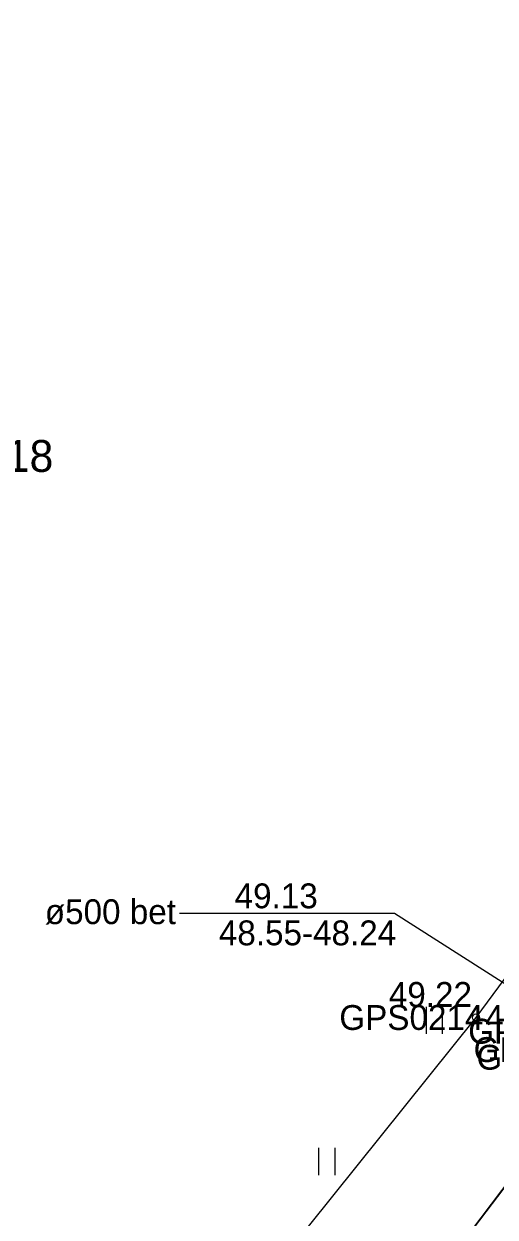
# Model space of a CAD drawing. Extents: x 563121 to 567545, y 6570841 to 6581299.
# Drawn here: x 565782.93 to 565796.21, y 6571844.15 to 6571877.77 of the extents above; entities that cross this region are included whole.
import ezdxf

# ---------------------------------------------------------------- set-up
doc = ezdxf.new("R2010")
doc.units = 0
for name, color, linetype in [('HALJASTUS', 7, 'Continuous'), ('KORGUS-EH2000', 7, 'Continuous'), ('MOOTKORG-EH2000', 7, 'Continuous'), ('MOOTMPUNKT', 7, 'Continuous'), ('MOOTNR', 7, 'Continuous'), ('MOOTPIIR', 7, 'Continuous'), ('PIIR', 7, 'Continuous'), ('TRUUP', 7, 'Continuous')]:
    doc.layers.add(name, color=color, linetype=linetype)

msp = doc.modelspace()

# ---------------------------------------------------------------- linework, layer by layer
at = {"layer": 'HALJASTUS'}
for p, q in [((565794.266, 6571850.073), (565794.266, 6571849.312)), ((565794.721, 6571850.073), (565794.721, 6571849.312)), ((565791.235, 6571846.096), (565791.235, 6571845.335)), ((565791.69, 6571846.096), (565791.69, 6571845.335))]:
    msp.add_line(p, q, dxfattribs=at)
at = {"layer": 'KORGUS-EH2000'}
msp.add_circle((565795.67, 6571849.773), 0.1, dxfattribs=at)
at = {"layer": 'MOOTMPUNKT'}
msp.add_circle((565795.67, 6571849.773), 0.1, dxfattribs=at)
at = {"layer": 'MOOTPIIR'}
msp.add_lwpolyline([(565823.283, 6571871.288), (565820.939, 6571873.864), (565815.364, 6571875.639), (565813.463, 6571874.16), (565808.89, 6571868.083), (565802.021, 6571858.377), (565795.67, 6571849.773), (565782.207, 6571833.008), (565776.308, 6571825.832), (565781.278, 6571820.922), (565782.262, 6571820.691), (565783.542, 6571819.443), (565784.347, 6571818.115), (565785.017, 6571817.401), (565789.374, 6571812.429), (565790.175, 6571811.534), (565801.221, 6571799.668)], dxfattribs=at)
at = {"layer": 'PIIR'}
msp.add_lwpolyline([(564959.63, 6571567.88), (565247.22, 6571575.87), (565310, 6571592), (565385.09, 6571617.94), (565603.34, 6571696.36), (565663.71, 6571724.88), (565720.01, 6571762.52), (565767.05, 6571806.3), (565831.51, 6571891.07), (565894.85, 6571978.6), (565929.68, 6572026.82), (566028.25, 6572163.26), (566043.71, 6572184.75), (566068.58, 6572219.3), (566114.67, 6572283.35)], dxfattribs=at)
msp.add_lwpolyline([(565385.09, 6571617.94), (565348.3, 6571706.93), (565808.88, 6572174.3), (565817.95, 6572187.54), (565914.67, 6572223.63), (565927.34, 6572201.79), (566013.66, 6572213.36), (566028.25, 6572163.26), (565929.68, 6572026.82), (565869.35, 6572071.5), (565833.75, 6572019.48), (565773.79, 6571931.89), (565831.51, 6571891.07), (565767.05, 6571806.3), (565720.01, 6571762.52), (565663.71, 6571724.88), (565603.34, 6571696.36)], close=True, dxfattribs=at)
at = {"layer": 'TRUUP'}
msp.add_lwpolyline([(565800.195, 6571848.355), (565793.374, 6571852.7), (565787.316, 6571852.7)], dxfattribs=at)

# ---------------------------------------------------------------- texts
at = {"layer": 'KORGUS-EH2000'}
msp.add_text(' 49.22', height=0.7, dxfattribs=at).set_placement((565792.955, 6571850.073))
at = {"layer": 'MOOTKORG-EH2000'}
msp.add_text(' 49.22', height=0.7, dxfattribs=at).set_placement((565795.67, 6571849.423))
at = {"layer": 'MOOTNR'}
for s, p in [('GPS0214 ', (565791.82, 6571849.423)), ('GPS0210 ', (565795.451, 6571849.038)), ('GPS0209 ', (565795.604, 6571848.519)), ('GPS0211 ', (565795.683, 6571848.303))]:
    msp.add_text(s, height=0.7, dxfattribs=at).set_placement(p)
at = {"layer": 'PIIR'}
msp.add_text('65101:004:0118', height=0.9, dxfattribs=at).set_placement((565775.062, 6571865.147))
at = {"layer": 'TRUUP'}
for s, p in [('49.13', (565788.871, 6571852.851)), ('ø500 bet', (565783.523, 6571852.404)), ('48.55-48.24', (565788.426, 6571851.808))]:
    msp.add_text(s, height=0.7, dxfattribs=at).set_placement(p)

doc.saveas('drawing.dxf')
